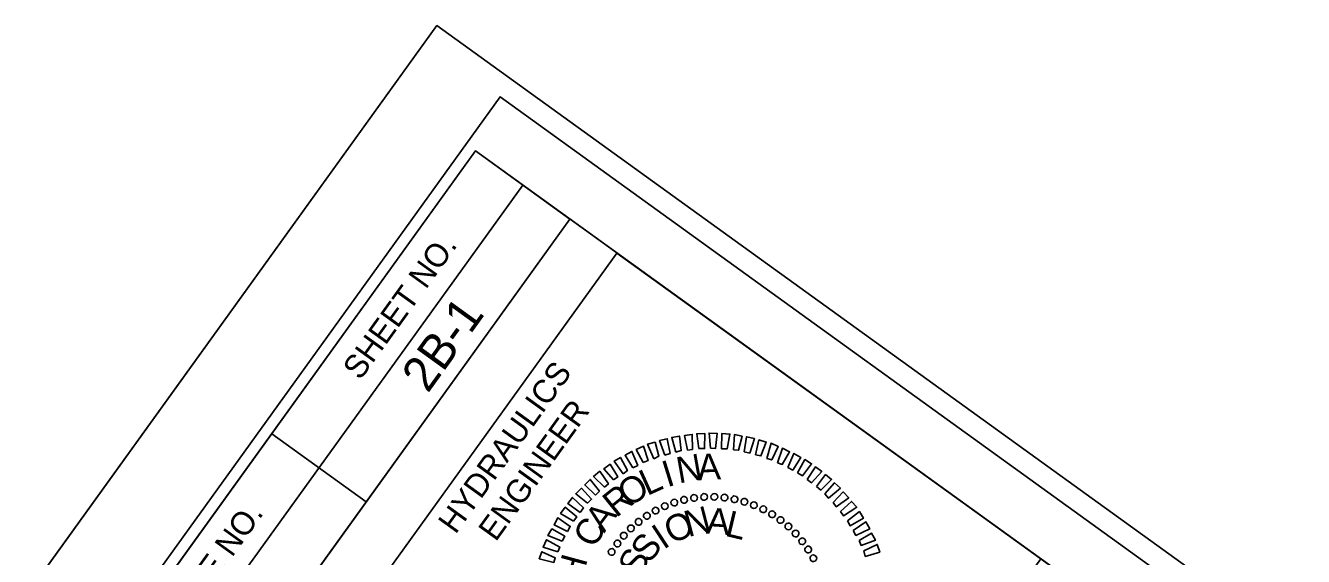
# Model space of a CAD drawing. Extents: x 2189185 to 2191058, y 386509 to 388561.
# Drawn here: x 2190081.4 to 2190356.5, y 388401.3 to 388515.4 of the extents above; entities that cross this region are included whole.
import ezdxf

# ---------------------------------------------------------------- set-up
doc = ezdxf.new("R2010")
doc.units = 0
for name, color, linetype in [('Sheet Cutting Line CELL', 7, 'Continuous'), ('Sheet Data Field CELL', 7, 'Continuous'), ('Sheet Plan CELL', 7, 'Continuous'), ('Sheet Plan Layout CELL', 7, 'Continuous'), ('Sheet Plot Border Inside CELL', 7, 'Continuous'), ('Sheet Plot Border Outside CELL', 7, 'Continuous'), ('Sheet Professional Seal CELL', 7, 'Continuous')]:
    doc.layers.add(name, color=color, linetype=linetype)

msp = doc.modelspace()

# ---------------------------------------------------------------- linework, layer by layer
at = {"layer": 'Sheet Cutting Line CELL'}
msp.add_line((2190169.94, 388515.44), (2189185.21, 387149.98), dxfattribs=at)
at = {"layer": 'Sheet Plan CELL'}
for p, q in [((2190071.39, 388318.9), (2190188.41, 388481.15)), ((2190081.56, 388311.57), (2190198.55, 388473.83)), ((2190081.56, 388311.57), (2190198.55, 388473.83)), ((2190134.4, 388427.6), (2190154.7, 388413.02))]:
    msp.add_line(p, q, dxfattribs=at)
for points in [[(2190178.25, 388488.52), (2189300.83, 387271.86), (2190152.47, 386657.68), (2191029.88, 387874.32)], [(2190061.21, 388326.25), (2190178.25, 388488.52), (2190198.55, 388473.83), (2190081.56, 388311.57)], [(2190150.21, 388385.42), (2190208.69, 388466.52), (2190299.95, 388400.72), (2190241.47, 388319.6)]]:
    msp.add_lwpolyline(points, close=True, dxfattribs=at)
at = {"layer": 'Sheet Plan Layout CELL'}
msp.add_lwpolyline([(2190209.82, 388170.73), (2190349.78, 388364.8), (2190178.26, 388488.53), (2190038.29, 388294.44)], close=True, dxfattribs=at)
at = {"layer": 'Sheet Plot Border Inside CELL'}
msp.add_lwpolyline([(2190064.73, 386531.72), (2191039.21, 387882.98), (2190183.53, 388500.09), (2189209.04, 387148.83)], close=True, dxfattribs=at)
at = {"layer": 'Sheet Plot Border Outside CELL'}
msp.add_lwpolyline([(2190073.35, 386509.48), (2191058.08, 387874.94), (2190169.94, 388515.44), (2189185.21, 387149.98)], close=True, dxfattribs=at)
at = {"layer": 'Sheet Professional Seal CELL'}
for p, q in [((2190225.26, 388413.86), (2190225.26, 388413.86)), ((2190227.48, 388414.11), (2190227.48, 388414.11)), ((2190229.63, 388414.1), (2190229.63, 388414.1)), ((2190231.84, 388413.92), (2190231.84, 388413.92)), ((2190217, 388411.13), (2190217, 388411.13)), ((2190218.96, 388412.12), (2190218.96, 388412.12)), ((2190221.02, 388412.85), (2190221.02, 388412.85)), ((2190223.14, 388413.48), (2190223.14, 388413.48)), ((2190234.01, 388413.59), (2190234.01, 388413.59)), ((2190236.1, 388413.07), (2190236.1, 388413.07)), ((2190238.16, 388412.33), (2190238.16, 388412.33)), ((2190240.17, 388411.37), (2190240.17, 388411.37)), ((2190213.31, 388408.74), (2190213.31, 388408.74)), ((2190215.1, 388410.03), (2190215.1, 388410.03)), ((2190242.09, 388410.36), (2190242.09, 388410.36)), ((2190243.91, 388409.11), (2190243.91, 388409.11)), ((2190210.17, 388405.76), (2190210.17, 388405.76)), ((2190211.72, 388407.3), (2190211.72, 388407.3)), ((2190245.6, 388407.7), (2190245.6, 388407.7)), ((2190247.14, 388406.16), (2190247.14, 388406.16)), ((2190208.77, 388404.06), (2190208.77, 388404.06)), ((2190248.58, 388404.57), (2190248.58, 388404.57)), ((2190249.88, 388402.77), (2190249.88, 388402.77)), ((2190207.52, 388402.25), (2190207.52, 388402.25))]:
    msp.add_line(p, q, dxfattribs=at)
for points in [[(2190223.85, 388424.13), (2190223.2, 388427.25), (2190224.88, 388427.52), (2190224.94, 388424.27)], [(2190226.34, 388424.49), (2190225.86, 388427.67), (2190227.57, 388427.74), (2190227.56, 388424.48)], [(2190228.8, 388424.57), (2190228.52, 388427.78), (2190230.26, 388427.71), (2190229.92, 388424.5)], [(2190231.22, 388424.42), (2190231.23, 388427.69), (2190233, 388427.58), (2190232.44, 388424.41)], [(2190233.76, 388424.19), (2190233.98, 388427.49), (2190235.62, 388427.11), (2190234.88, 388424.12)], [(2190214.36, 388421.48), (2190212.84, 388424.24), (2190214.41, 388424.96), (2190215.4, 388421.9)], [(2190216.6, 388422.27), (2190215.27, 388425.39), (2190216.88, 388425.83), (2190217.73, 388422.81)], [(2190219.01, 388423.06), (2190217.86, 388426.17), (2190219.52, 388426.58), (2190220.14, 388423.42)], [(2190221.38, 388423.69), (2190220.47, 388426.87), (2190222.15, 388427.15), (2190222.54, 388424.02)], [(2190236.09, 388423.75), (2190236.6, 388427.02), (2190238.28, 388426.61), (2190237.28, 388423.51)], [(2190238.52, 388423.1), (2190239.25, 388426.34), (2190240.83, 388425.87), (2190239.67, 388422.89)], [(2190240.94, 388422.35), (2190241.88, 388425.61), (2190243.39, 388424.89), (2190242, 388422.02)], [(2190210, 388419.02), (2190208.11, 388421.79), (2190209.42, 388422.58), (2190210.95, 388419.74)], [(2190212.08, 388420.29), (2190210.42, 388423.03), (2190211.9, 388423.87), (2190213.17, 388420.86)], [(2190243.24, 388421.43), (2190244.31, 388424.54), (2190245.86, 388423.79), (2190244.26, 388421.06)], [(2190245.45, 388420.39), (2190246.78, 388423.44), (2190248.25, 388422.56), (2190246.54, 388419.85)], [(2190247.57, 388419.23), (2190249.14, 388422.1), (2190250.58, 388421.19), (2190248.6, 388418.61)], [(2190206.02, 388416.15), (2190203.67, 388418.46), (2190204.99, 388419.6), (2190206.84, 388416.86)], [(2190207.95, 388417.72), (2190205.87, 388420.14), (2190207.19, 388421.1), (2190208.85, 388418.37)], [(2190249.63, 388417.81), (2190251.4, 388420.53), (2190252.78, 388419.54), (2190250.6, 388417.11)], [(2190204.08, 388414.41), (2190201.75, 388416.64), (2190202.92, 388417.83), (2190204.9, 388415.29)], [(2190251.62, 388416.3), (2190253.61, 388418.88), (2190254.89, 388417.84), (2190252.54, 388415.52)], [(2190253.42, 388414.7), (2190255.54, 388417.12), (2190256.8, 388415.96), (2190254.25, 388413.79)], [(2190200.77, 388410.75), (2190198.13, 388412.65), (2190199.14, 388413.96), (2190201.51, 388411.7)], [(2190202.35, 388412.69), (2190199.83, 388414.76), (2190201.04, 388415.92), (2190203.22, 388413.55)], [(2190255.26, 388412.88), (2190257.4, 388415.16), (2190258.57, 388413.88), (2190255.88, 388411.94)], [(2190199.32, 388408.84), (2190196.54, 388410.53), (2190197.55, 388411.84), (2190200.07, 388409.78)], [(2190256.82, 388410.95), (2190259.17, 388413.09), (2190260.3, 388411.84), (2190257.44, 388410.01)], [(2190198.06, 388406.66), (2190195.15, 388408.09), (2190195.98, 388409.58), (2190198.64, 388407.72)], [(2190258.33, 388408.94), (2190260.88, 388410.93), (2190261.75, 388409.49), (2190258.86, 388407.88)], [(2190259.53, 388406.84), (2190262.28, 388408.68), (2190263.1, 388407.17), (2190260.13, 388405.79)], [(2190196.9, 388404.54), (2190193.84, 388405.76), (2190194.68, 388407.19), (2190197.48, 388405.6)], [(2190260.81, 388404.68), (2190263.49, 388406.27), (2190264.31, 388404.75), (2190261.23, 388403.64)], [(2190195.95, 388402.27), (2190192.78, 388403.26), (2190193.49, 388404.85), (2190196.36, 388403.27)], [(2190261.85, 388402.45), (2190264.71, 388403.85), (2190265.26, 388402.22), (2190262.12, 388401.28)], [(2190195.07, 388399.94), (2190191.96, 388400.77), (2190192.51, 388402.29), (2190195.4, 388401)]]:
    msp.add_lwpolyline(points, close=True, dxfattribs=at)
for centre, major_axis in [((2190223.13, 388413.43), (-0.164, 0.701)), ((2190225.28, 388413.84), (-0.103, 0.713)), ((2190227.46, 388414.06), (-0.04, 0.719)), ((2190229.65, 388414.08), (0.023, 0.72)), ((2190231.83, 388413.92), (0.085, 0.715)), ((2190233.99, 388413.56), (0.147, 0.705)), ((2190236.11, 388413.02), (0.208, 0.689)), ((2190217.01, 388411.12), (-0.34, 0.635)), ((2190218.98, 388412.07), (-0.284, 0.662)), ((2190221.03, 388412.84), (-0.225, 0.684)), ((2190238.17, 388412.3), (0.267, 0.669)), ((2190240.17, 388411.4), (0.325, 0.643)), ((2190242.08, 388410.33), (0.379, 0.612)), ((2190213.35, 388408.72), (-0.445, 0.566)), ((2190215.13, 388410), (-0.394, 0.602)), ((2190243.88, 388409.1), (0.431, 0.577)), ((2190245.58, 388407.71), (0.48, 0.537)), ((2190210.16, 388405.73), (-0.537, 0.48)), ((2190211.69, 388407.3), (-0.493, 0.525)), ((2190247.14, 388406.18), (0.525, 0.493)), ((2190207.54, 388402.23), (-0.612, 0.379)), ((2190208.78, 388404.04), (-0.577, 0.431)), ((2190248.57, 388404.52), (0.566, 0.445)), ((2190249.85, 388402.75), (0.602, 0.394)), ((2190250.96, 388400.87), (0.635, 0.34))]:
    msp.add_ellipse(centre, major_axis=major_axis, ratio=0.999708, dxfattribs=at)

# ---------------------------------------------------------------- texts
at = {"layer": 'Sheet Data Field CELL'}
msp.add_text('2B-1', height=7.5, rotation=54.2018, dxfattribs=at).set_placement((2190167.96, 388436.2))
at = {"layer": 'Sheet Plan CELL'}
for s, height, p in [('SHEET NO.', 5, (2190153.41, 388438.98)), ('HYDRAULICS', 5, (2190173.93, 388405.87)), ('ENGINEER', 5, (2190182.59, 388404.26)), ('PROJECT REFERENCE NO.', 5.0001, (2190081.28, 388339.15))]:
    msp.add_text(s, height=height, rotation=54.2018, dxfattribs=at).set_placement(p)
at = {"layer": 'Sheet Professional Seal CELL'}
for s, rotation, p in [('N', 10.0208, (2190222.01, 388416.95)), ('A', 2.819, (2190226.12, 388417.62)), ('L', 24.4227, (2190215.18, 388414.23)), ('I', 17.222, (2190219.49, 388416.11)), ('O', 31.623, (2190211.1, 388411.75)), ('R', 38.8229, (2190208.53, 388409.47)), ('A', 53.2222, (2190205.92, 388406.18)), ('N', 14.6785, (2190224.02, 388405.39)), ('A', 355.9621, (2190227.8, 388406.18)), ('L', 346.6027, (2190231.74, 388405.74)), ('C', 60.4217, (2190203.85, 388402.8)), ('O', 24.0353, (2190220.44, 388403.84)), ('S', 52.1022, (2190215.62, 388399.55)), ('I', 33.3914, (2190218.7, 388402.63)), ('S', 61.4575, (2190213.56, 388396.6)), ('H', 74.8213, (2190201.02, 388395.46))]:
    msp.add_text(s, height=5.64, rotation=rotation, dxfattribs=at).set_placement(p)

doc.saveas('drawing.dxf')
